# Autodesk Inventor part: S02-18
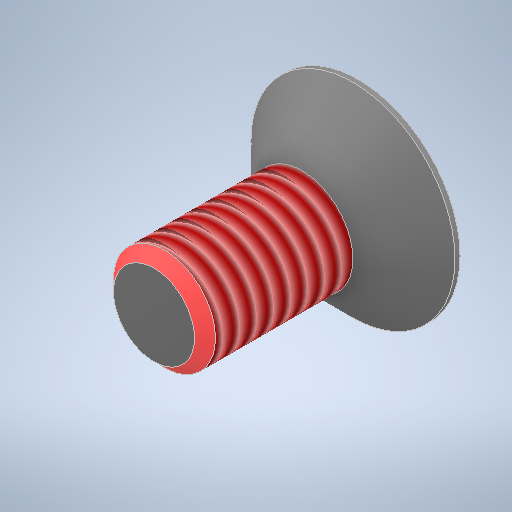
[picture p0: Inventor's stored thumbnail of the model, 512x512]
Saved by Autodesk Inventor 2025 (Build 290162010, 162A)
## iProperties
Manager: DIN 7991
Created: 2025-04
Part Number: S02-18
Material: Všeobecné
Document SubType Name: Modeling
Designer: Patrik
Density: 1 g/cm^3
Appearance: Výchozí
Description: Šroub se zápustnou hlavou a vnitřním šestihranem
Stock Number: E 1220/6x12
Mass: 0.439874 g
Surface Area: 4.63988 cm^2
Volume: 0.439874 cm^3
User Status: 10.9
Sending System: KiM GmbH
Major Version: 4.0
Minor Version: 0.0
Format Version: 0.0
Product Id: KiM GmbH
cc_prop_force_one_body: 1
Hersteller: Meusburger
Material: 10.9 DIN 7991
Bestellnummer: E 1220/6x12
Teilenummer: E 1220/6x12
Beschreibung: Senkkopfschraube mit Innensechskant _ Countersunk head screw with hexagon socket
Author: Patrik
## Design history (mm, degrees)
feature "E 1220_6x12_1_1:1"
feature "Závit1" dims "d0" = 8.085, "d1" = 0
node "Těleso1"
